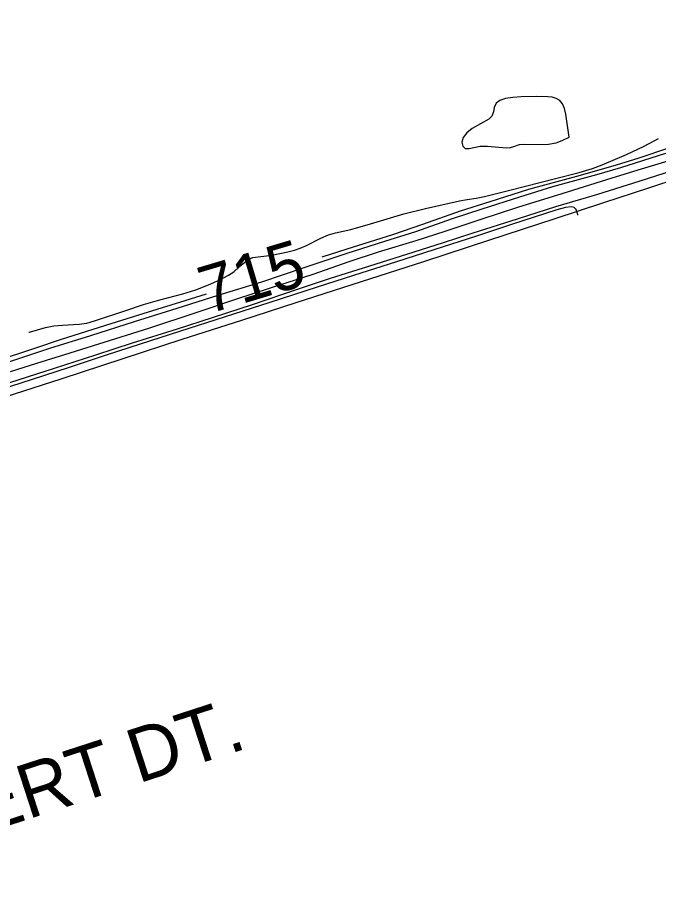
# Model space of a CAD drawing. Extents: x -468563856 to 36492962, y -306094093 to 11899197.
# Drawn here: x 1819604 to 1820050, y 529943 to 530558 of the extents above; entities that cross this region are included whole.
import ezdxf

# ---------------------------------------------------------------- set-up
doc = ezdxf.new("R2010")
doc.units = 0
for name, color, linetype in [('DT_X_Contour_Minor', 7, 'Continuous'), ('Level 14', 7, 'Continuous'), ('Level 19', 7, 'Continuous'), ('Level 40', 7, 'Continuous')]:
    doc.layers.add(name, color=color, linetype=linetype)

msp = doc.modelspace()

# ---------------------------------------------------------------- linework, layer by layer
at = {"layer": 'DT_X_Contour_Minor'}
for points in [[(1820338.6, 530558.33), (1820321.94, 530553.17), (1820293.38, 530544.36), (1820270.69, 530536.04), (1820252.92, 530529.64), (1820230.39, 530522.49), (1820206.59, 530514.86), (1820178, 530505.51), (1820153.03, 530497.31), (1820124.29, 530488.06), (1820098.86, 530480.92), (1820080.14, 530475.45), (1820057.92, 530467.7), (1820035.86, 530460.29), (1820018.33, 530454.81), (1819993.18, 530447.62), (1819959.63, 530438.56), (1819932.76, 530430.1), (1819912.01, 530423.44), (1819885.79, 530414.17), (1819864.83, 530406.97), (1819837.4, 530398.39), (1819816.27, 530391.63), (1819815.75, 530391.46)], [(1819988.08, 530475), (1819985.75, 530491), (1819984.84, 530494.99), (1819983.44, 530498.33), (1819981.39, 530500.66), (1819978.86, 530502.11), (1819976.05, 530502.91), (1819973.11, 530503.29), (1819965.55, 530503.37), (1819954.5, 530503.17), (1819948.77, 530502.78), (1819943.73, 530502.01), (1819939.72, 530500.69), (1819937.06, 530498.66), (1819935.83, 530495.85), (1819935.22, 530492.72), (1819934.18, 530489.82), (1819931.92, 530487.54), (1819920.44, 530481.01), (1819916.7, 530478.04), (1819914.12, 530474.8), (1819913.22, 530471.5), (1819913.84, 530468.72), (1819915.64, 530467.13), (1819918.33, 530467.12), (1819926.09, 530468.81), (1819930.99, 530468.85), (1819944.3, 530467.71), (1819947.14, 530467.95), (1819949.34, 530468.48), (1819953.4, 530469.89), (1819956.74, 530470.24), (1819967.67, 530469.92), (1819973.66, 530470.17), (1819978.89, 530471.2), (1819983.03, 530472.65), (1819988.08, 530475)], [(1819611.58, 530339.18), (1819611.88, 530339.26), (1819623.14, 530342.42), (1819628.94, 530343.51), (1819634.91, 530344.02), (1819646.51, 530344.67), (1819651.81, 530345.58), (1819657.23, 530347.05), (1819678.36, 530354.18), (1819691.32, 530358.5), (1819702.74, 530361.74), (1819718.77, 530365.96), (1819727.8, 530368.81), (1819736.62, 530372.18), (1819744.47, 530375.7), (1819750.58, 530378.87), (1819754.44, 530381.34), (1819758.32, 530384.85), (1819761.82, 530387.82), (1819766.1, 530390.85), (1819767.51, 530391.3), (1819780.8, 530392.76), (1819792.02, 530395.09), (1819796.59, 530396.32), (1819800.67, 530397.75), (1819804.89, 530399.62), (1819814.98, 530404.69), (1819820.22, 530406.93), (1819825.19, 530408.44), (1819835.93, 530410.8), (1819849.57, 530414.62), (1819872.79, 530421.59), (1819887.85, 530425.39), (1819911.67, 530430.77), (1819916.93, 530431.68), (1819923.13, 530432.55), (1819928.91, 530433.75), (1819946.68, 530438.15), (1819978.53, 530446.28), (1819995.07, 530450.45), (1820004.31, 530453.19), (1820011.1, 530455.82), (1820027.83, 530463.05), (1820040.2, 530468.81), (1820050.15, 530474.11)], [(1820055.03, 530463.63), (1820023.65, 530453.82), (1820007.15, 530448.86), (1819976.34, 530440.4), (1819953.39, 530433.27), (1819927.12, 530424.97), (1819906.57, 530418.08), (1819881.03, 530409.21), (1819859.36, 530402.34), (1819833.1, 530394.06), (1819803.85, 530384.18), (1819773.55, 530374.13), (1819743.14, 530364.83), (1819714.73, 530355.73), (1819684.97, 530346.41), (1819654.57, 530336.71), (1819625.91, 530327.72), (1819596.04, 530317.94)], [(1819598.82, 530311.77), (1819616.96, 530317.59), (1819640.21, 530324.91), (1819672.1, 530334.79), (1819695.03, 530342.07), (1819728.03, 530352.79), (1819755.68, 530362.15), (1819779.91, 530370.03), (1819809.63, 530379.67), (1819834.72, 530388.34), (1819855.12, 530395.21), (1819881.35, 530403.18), (1819901.64, 530409.54), (1819926.73, 530417.98), (1819952.31, 530426.27), (1819983.05, 530435.76), (1820014.23, 530445.65), (1820035.98, 530452.21), (1820073.33, 530463.49)], [(1820060.51, 530451.95), (1820036.58, 530444.21), (1820007.69, 530435.13), (1819978.38, 530426.42), (1819952.55, 530418.23), (1819920.23, 530407.99), (1819900.16, 530401.5), (1819874.69, 530393.4), (1819844.46, 530383.9), (1819821.51, 530376.5), (1819798.49, 530368.95), (1819767.05, 530358.18), (1819739.27, 530349.17), (1819714.75, 530341.31), (1819683.51, 530331.48), (1819658.05, 530323.21), (1819629.11, 530313.79), (1819598.14, 530303.81)], [(1819993.93, 530420.75), (1819993.96, 530421.25), (1819992.82, 530424.67), (1819991.59, 530426.03), (1819989.29, 530426.63), (1819985.37, 530426.1), (1819979.35, 530424.42), (1819947.87, 530414.15), (1819923.4, 530406.14), (1819893.59, 530396.49), (1819867.69, 530388.21), (1819837.75, 530378.69), (1819812.34, 530370.63), (1819779.45, 530359.97), (1819748.24, 530349.86), (1819716.38, 530339.62), (1819689.11, 530330.8), (1819665.43, 530323.08), (1819638.87, 530314.4), (1819613.71, 530306.27), (1819584.05, 530296.78)], [(1819735.12, 530365.57), (1819720.1, 530360.98), (1819690.82, 530351.97), (1819665.02, 530343.81), (1819633.43, 530333.77), (1819616.08, 530328.1), (1819587.14, 530318.56), (1819563.46, 530310.78), (1819539.22, 530302.91), (1819512.34, 530294.19), (1819496.73, 530288.95), (1819465.07, 530278.01), (1819446.56, 530272.1), (1819418.4, 530263.17), (1819394.91, 530255.75), (1819362.75, 530245.73), (1819334.71, 530237.16), (1819310.42, 530229.54), (1819293.76, 530224.31)]]:
    msp.add_lwpolyline(points, dxfattribs=at)
at = {"layer": 'Level 14'}
msp.add_lwpolyline([(1820085.62, 530453.49), (1820043.35, 530439.51), (1820011.97, 530429.33), (1819977.27, 530417.86), (1819932.41, 530403.25), (1819886.48, 530388.28), (1819843.09, 530374.3), (1819797.62, 530359.69), (1819759.78, 530347.43), (1819718.07, 530333.98), (1819677.06, 530320.65), (1819633.68, 530306.46), (1819588.1, 530291.84), (1819544.63, 530277.68), (1819500.45, 530263.45), (1819456.73, 530249.26), (1819410.72, 530234.19), (1819363.8, 530218.94)], dxfattribs=at)

# ---------------------------------------------------------------- texts
at = {"layer": 'Level 19'}
msp.add_text('715', height=33, rotation=16.65015, dxfattribs=at).set_placement((1819736.02, 530351.66))
at = {"layer": 'Level 40'}
msp.add_text('WEIPPERT DT.', height=37.5, rotation=17.9864, dxfattribs=at).set_placement((1819425.3, 529939.42))

doc.saveas('drawing.dxf')
